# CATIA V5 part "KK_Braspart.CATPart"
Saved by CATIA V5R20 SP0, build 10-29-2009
Part number: bras
Bounding box of the stored display mesh (mm): x -529.891 to 370.019, y -156.493 to -56.493, z 0 to 50
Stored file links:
  G:\Khaled_CFAO_2011\ST2M\ST2M_GR2\tcorbin\Khaled\CAD_ThinkMOTION\KK_Braspart.CATPart
  F:\Thinkmotionperso\assemblage robot\ass_skl_robot.CATProduct
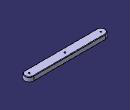
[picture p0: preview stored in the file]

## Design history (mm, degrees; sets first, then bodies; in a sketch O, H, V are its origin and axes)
External parameters (linked from other documents)
  `External.perçage avbrasbras` = 15 mm
  `External.perçage bras_arbre` = 15 mm
  `External.longueur bras` = 800 mm
  `External.largeur avbrasbras` = 100 mm
  `External.epaisseur avbrasbras` = 50 mm
Body1 (main body)
  Sketch1 on xy-plane, origin (0, 0, 0), H (1, 0, 0), V (0, 1, 0)
    line L1 (-479.9356, -56.4934) -> (320.0644, -56.4934)
    arc A1 centre (320.0644, -106.4934) radius 50 from (320.0644, -56.4934) to (320.0644, -156.4934) cw
    line L2 (320.0644, -156.4934) -> (-479.9356, -156.4934)
    arc A2 centre (-479.9356, -106.4934) radius 50 from (-479.9356, -156.4934) to (-479.9356, -56.4934) cw
    length L1 = 800 {= `External.longueur bras`}
    distance L1 L2 = 100 {= `External.largeur avbrasbras`}
    length L2 = 800 {= `External.longueur bras`}
    tangency: A1 L1, L2 A1, A2 L2
    horizontal: L1 H, L2 H
  Pad1: profile Sketch1, direction (0, 0, 1), length 50 {= `External.epaisseur avbrasbras`}
  Sketch2 on end face of Pad1, origin (129.1731, -79.5969, 50), H (1, 0, 0), V (0, 1, 0)
    point P1 (190.8913, -26.8965)
    reference projected line E1 (190.8913, 23.1035) -> (-609.1087, 23.1035) from edge [face of Pad1 from Sketch1.L1 | end face of Pad1]
    reference projected point E2 (190.8913, -76.8965) from vertex [face of Pad1 from Sketch1.A1 | end face of Pad1 | face of Pad1 from Sketch1.L2]
    distance P1 E1 = 50
    distance P1 E2 = 50
  Hole1: placed by Sketch2, at (320.0644, -106.4934, 50) direction (0, 0, -1), diameter 15 {= `External.perçage avbrasbras`}, through (limit type 3)
  Sketch3 on end face of Pad1, origin (-65.0391, -111.9918, 50), H (1, 0, 0), V (0, 1, 0)
    point P1 (-14.8965, 5.4984)
    reference projected line E1 (385.1035, 55.4984) -> (-414.8965, 55.4984) from edge [face of Pad1 from Sketch1.L1 | end face of Pad1]
    reference projected point E2 (385.1035, 5.4984) from Sketch2.P1
    distance P1 E1 = 50
    distance E2 P1 = 400
  Hole2: placed by Sketch3, at (-79.9356, -106.4934, 50) direction (0, 0, -1), diameter 15 {= `External.perçage bras_arbre`}, through (limit type 3)
  Sketch4 on end face of Pad1, origin (85.3036, -107.9083, 50), H (1, 0, 0), V (0, 1, 0)
    point P1 (-565.2392, 1.4149)
    reference projected point E1 (-565.2392, 51.4149) from vertex [face of Pad1 from Sketch1.L1 | end face of Pad1 | face of Pad1 from Sketch1.A2]
    reference projected line E2 (234.7608, 51.4149) -> (-565.2392, 51.4149) from edge [face of Pad1 from Sketch1.L1 | end face of Pad1]
    distance P1 E1 = 50
    distance P1 E2 = 50
  Hole3: placed by Sketch4, at (-479.9356, -106.4934, 50) direction (0, 0, -1), diameter 15, through (limit type 3)
  Fillet1: radius 5, on edge [face of Pad1 from Sketch1.L2 | end face of Pad1]; edge [face of Pad1 from Sketch1.L1 | end face of Pad1]; edge [face of Pad1 from Sketch1.A1 | end face of Pad1]; edge [face of Pad1 from Sketch1.A2 | end face of Pad1]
